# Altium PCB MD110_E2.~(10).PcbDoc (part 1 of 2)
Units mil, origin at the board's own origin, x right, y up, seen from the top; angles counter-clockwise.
Board outline 2320.51 x 1908 mil, 4 copper layers (Top Layer, Signal Layer 1, Signal Layer 2, Bottom Layer), stack 61.2 mil thick; 89 components, 32 nets, 187 pads, 40 vias.
Unrouted connection lines stored in the file: 7.
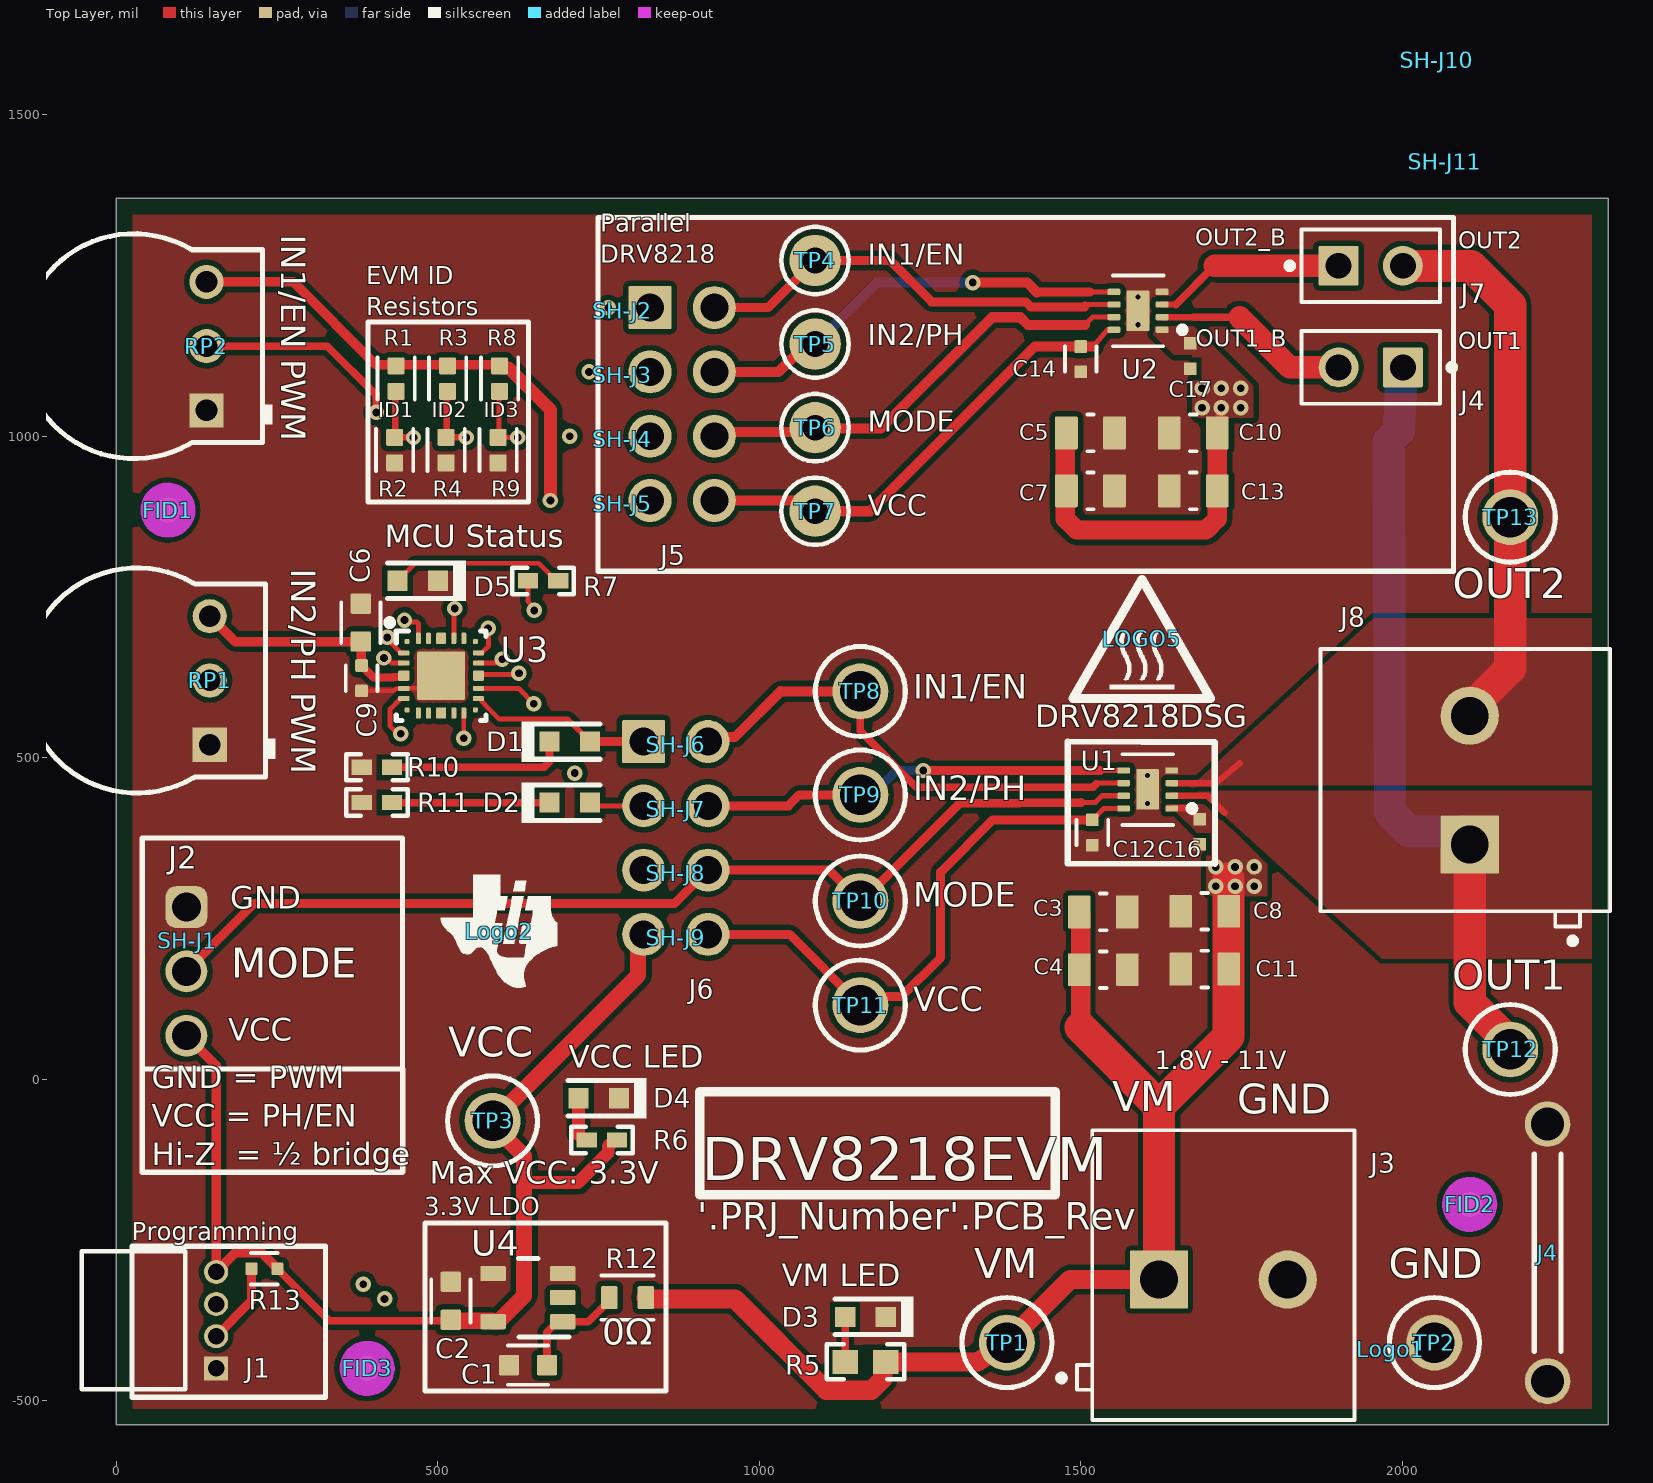
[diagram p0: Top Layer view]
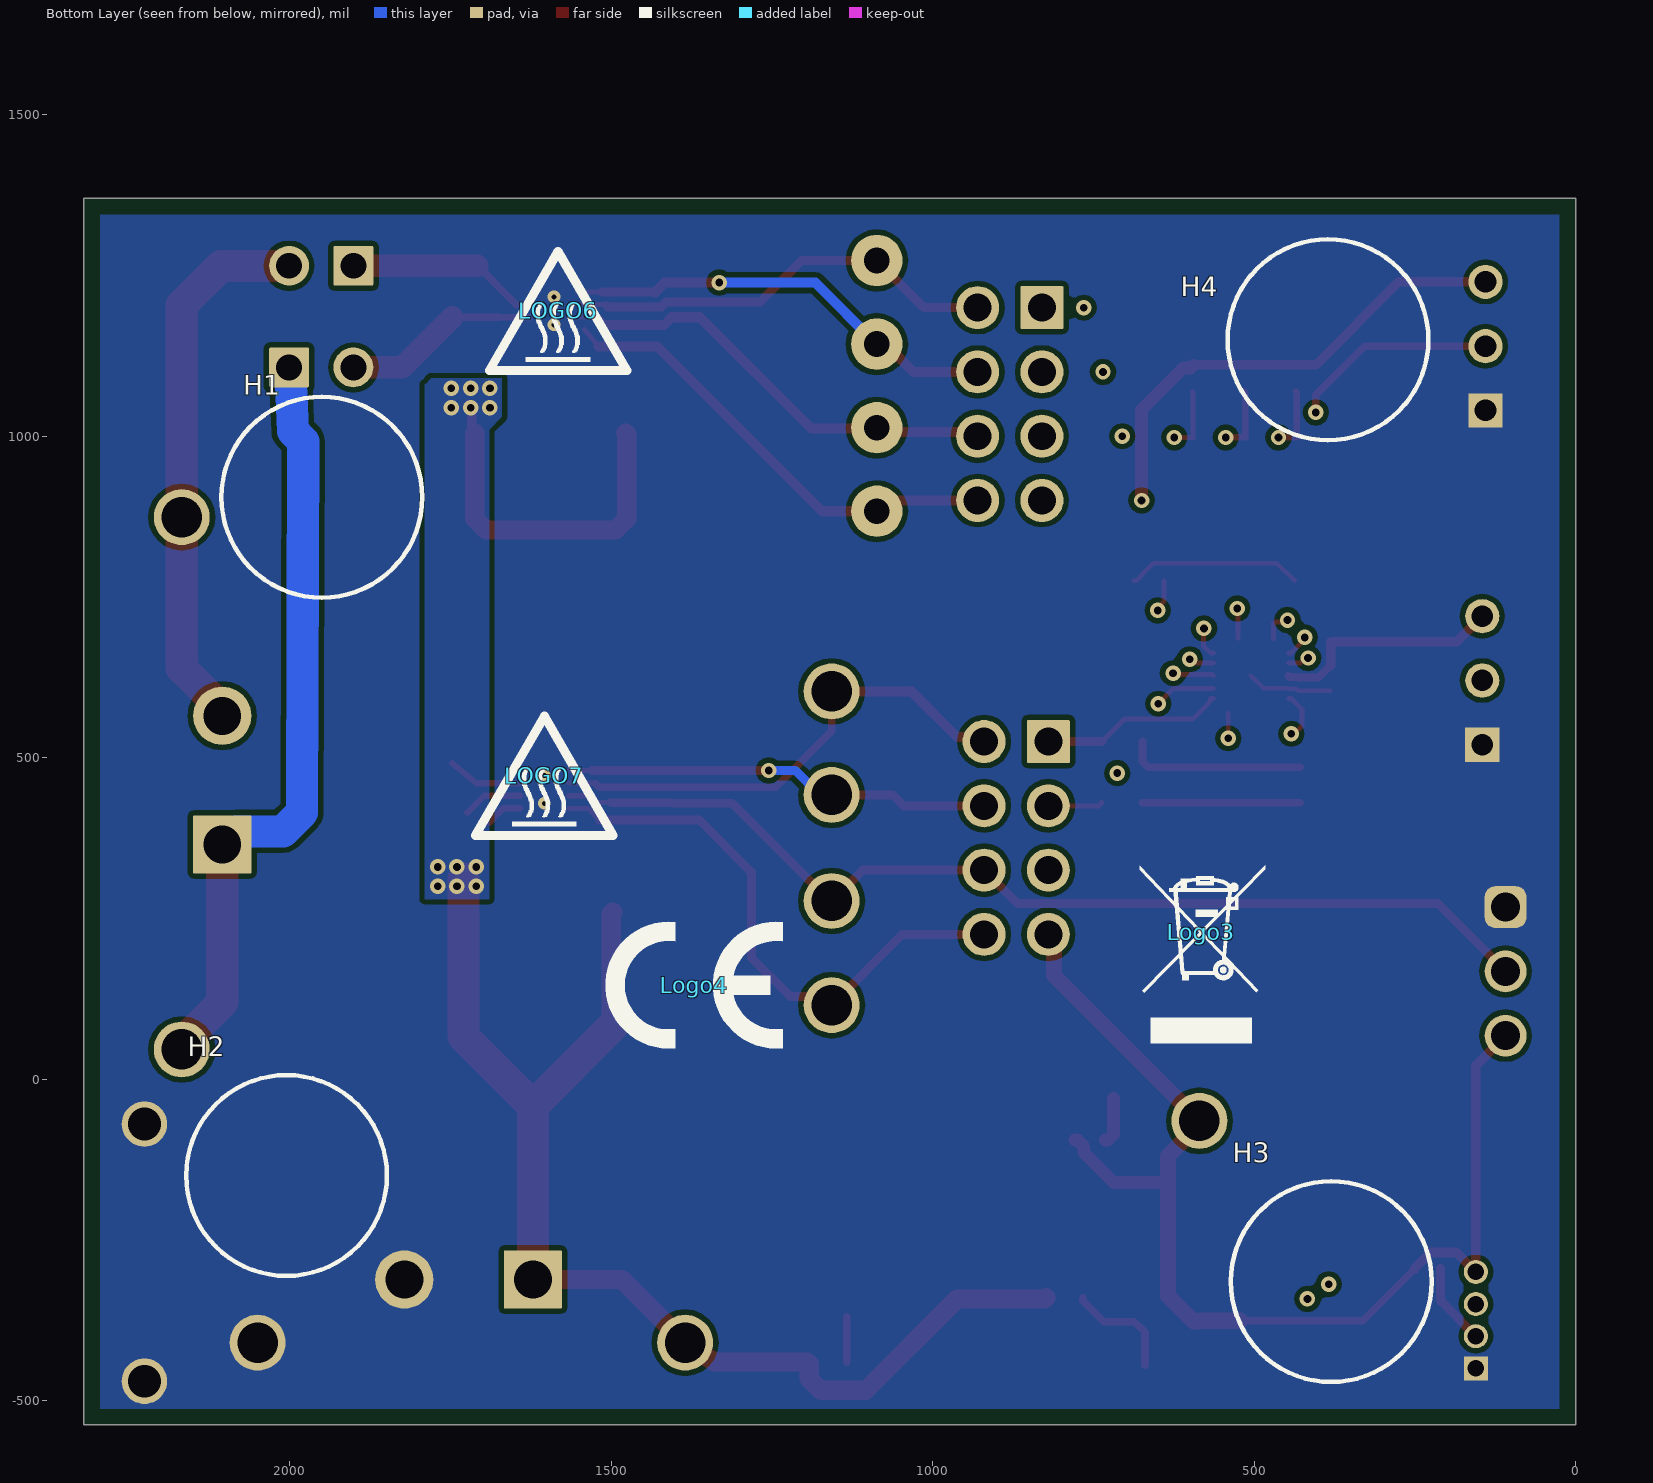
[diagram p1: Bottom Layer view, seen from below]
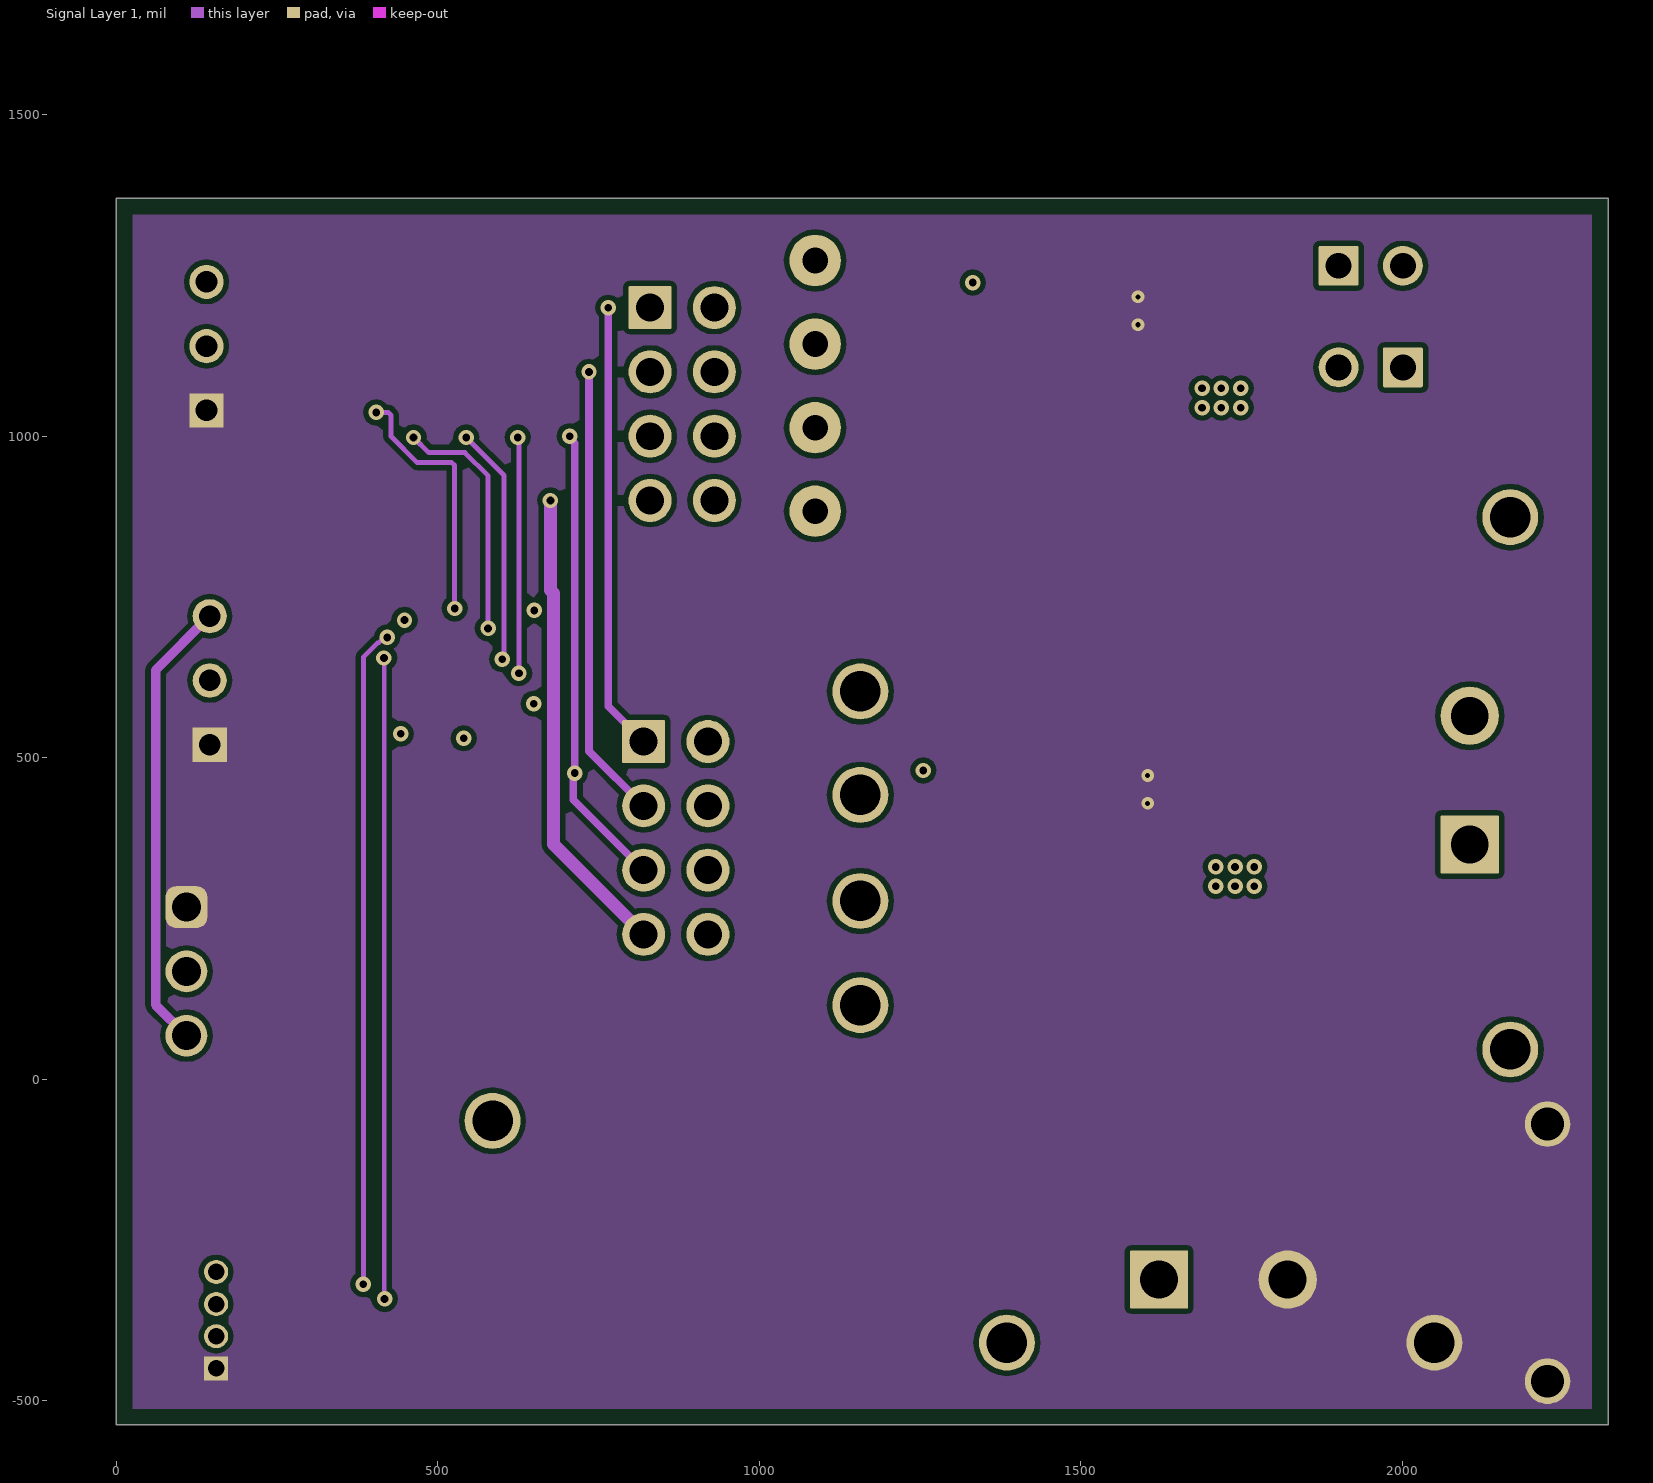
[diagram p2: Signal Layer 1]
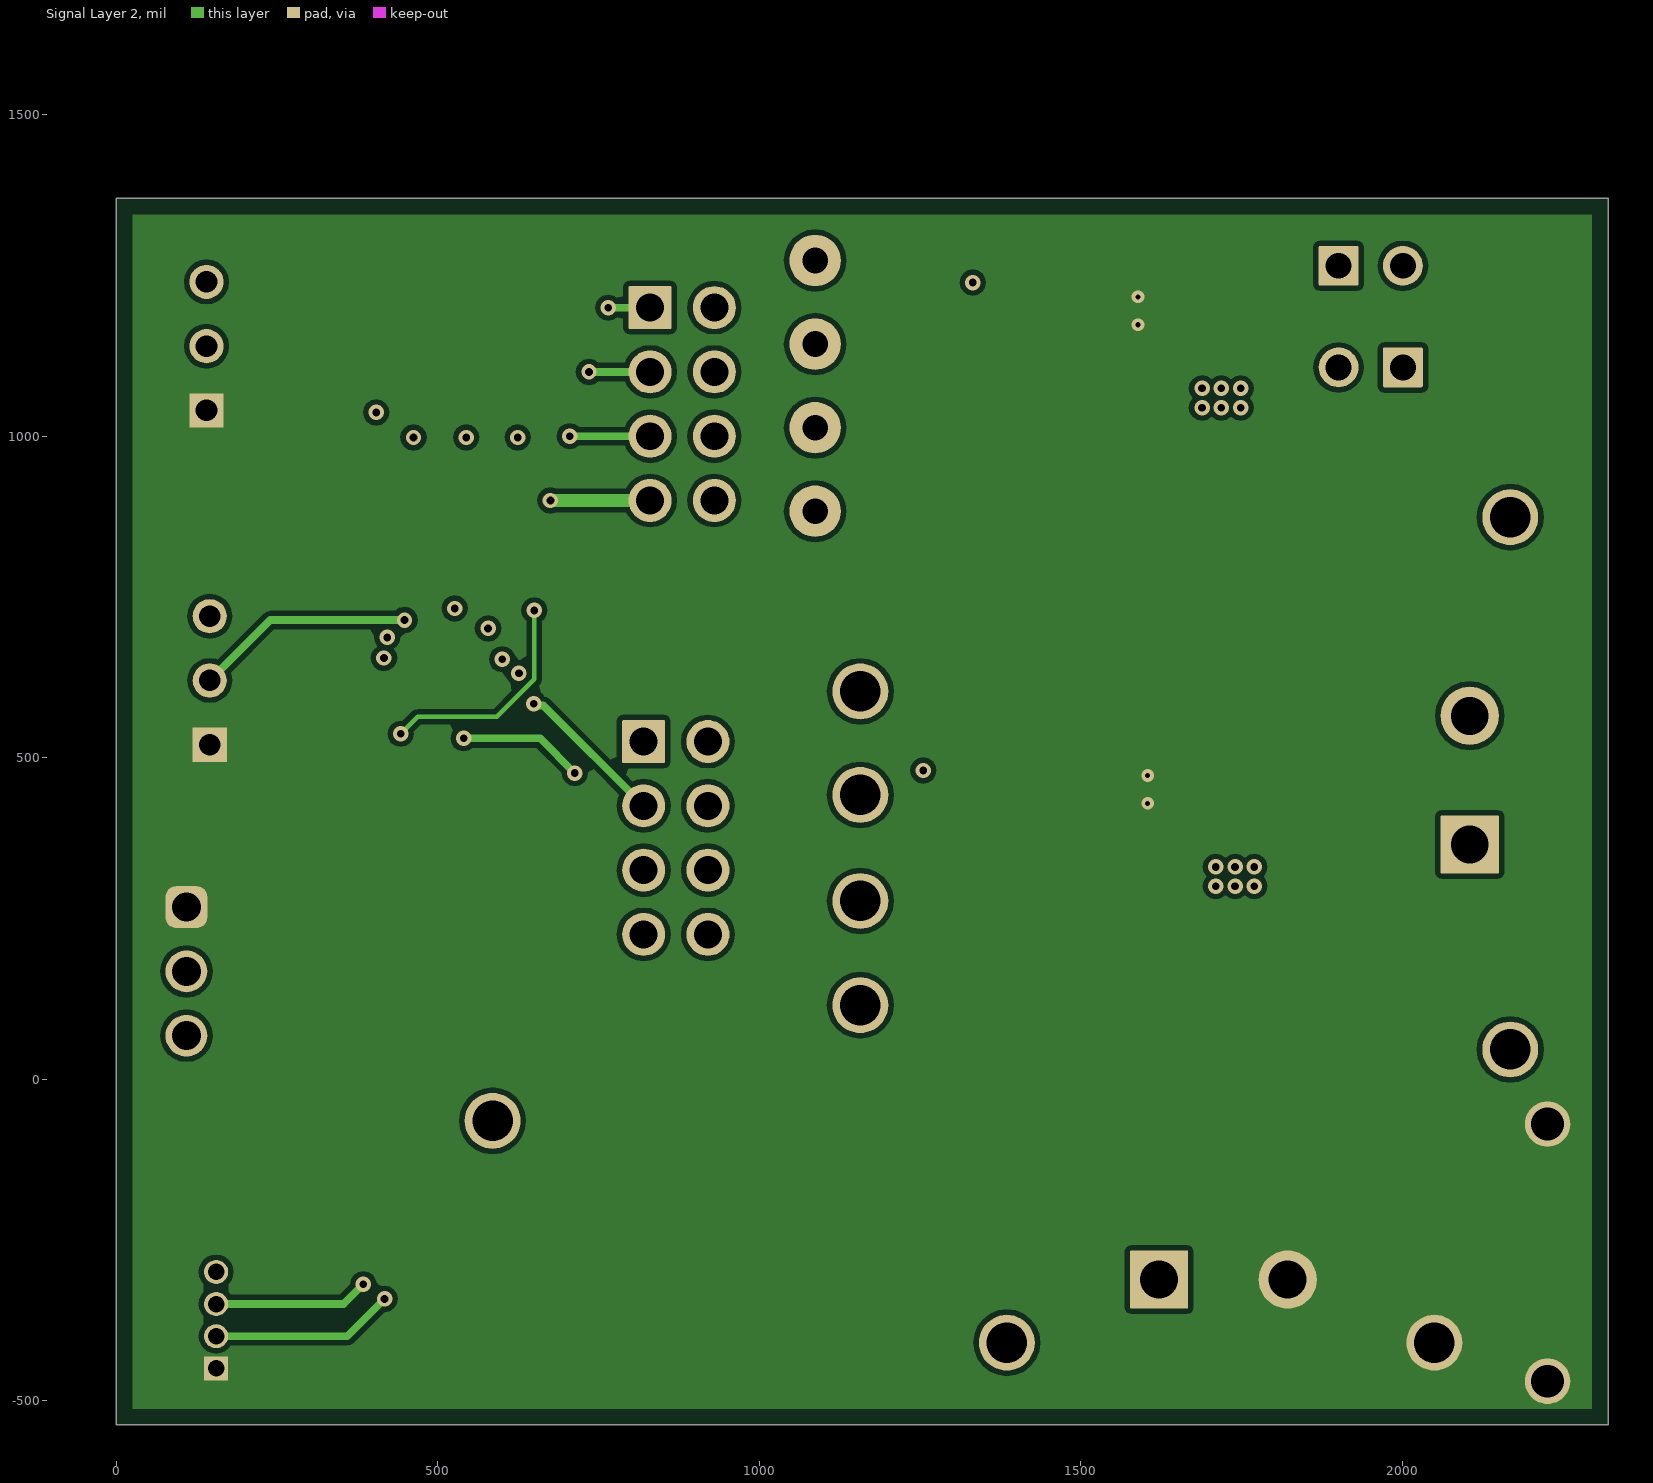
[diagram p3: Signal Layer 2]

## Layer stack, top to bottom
Top Solder: solder mask 0.4, Solder Resist, Dk 3.5
Top Layer: signal copper 2.8
Dielectric 1: prepreg 11.4, FR4 370, Dk 4.2
Signal Layer 1: signal copper 1.4
Dielectric 2: core 30, FR4 370, Dk 4.2
Signal Layer 2: signal copper 1.4
Dielectric 3: prepreg 11.4, FR4 370, Dk 4.2
Bottom Layer: signal copper 2.8
Bottom Solder: solder mask 0.4, Solder Resist, Dk 3.5

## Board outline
0,-538 0,1370 2320.51,1370 2320.51,-538

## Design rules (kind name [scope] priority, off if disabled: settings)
AcuteAngle [All] p1: minimum=4.50000000000000E+0001 checktracksonly=FALSE
AssemblyTestPointUsage [All] p1: valid=2
BoardOutlineClearance BoardOutlineClearance_MountingHoles [OnCopper and InComponentClass('Mounting Holes')] p1: gap=25 ignorepadtopadclearanceinfootprint=FALSE
BoardOutlineClearance BoardOutlineClearance_Poly [OnCopper and IsPoly] p2: gap=25 ignorepadtopadclearanceinfootprint=FALSE
BoardOutlineClearance [OnCopper and Not InComponentClass('Logo') and not InComponentClass('FiducialMark') and not InRegion(1000,500,4000,800) and not InPoly] p3: gap=10 ignorepadtopadclearanceinfootprint=FALSE
Clearance Clearance_OUTx [InNet('OUT1')] p1: gap=8 ignorepadtopadclearanceinfootprint=TRUE
Clearance Clearance_Keepouts [((IsTrack Or IsArc) And Not InPoly) And IsFree and IsKeepOut vs ((IsTrack Or IsArc) And Not InPoly) And IsFree and IsKeepOut] p2: gap=0 ignorepadtopadclearanceinfootprint=FALSE
Clearance Clearance_FiducialMark [IsKeepOut and InComponentClass('FiducialMark') vs IsPad and InComponentClass('FiducialMark')] p3: gap=0 ignorepadtopadclearanceinfootprint=FALSE
Clearance Clearance_Poly [InPolygon] p4: gap=8 ignorepadtopadclearanceinfootprint=TRUE
Clearance [All] p5: gap=7.87 ignorepadtopadclearanceinfootprint=TRUE
ComponentClearance ComponentClearance_Shunt2Header [InComponentClass('Header') vs InComponentClass('Shunt')] p1: gap=0 collisioncheckmode=3 verticalgap=0 showdistances=FALSE
ComponentClearance ComponentClearance_Shunt2Shunt [InComponentClass('Shunt') vs InComponentClass('Shunt')] p2: gap=0 collisioncheckmode=3 verticalgap=0 showdistances=FALSE
ComponentClearance ComponentClearance_MountingHoles_FiducialMarks [InComponentClass('Mounting Holes') vs InComponentClass('FiducialMark')] p3: gap=50 collisioncheckmode=3 verticalgap=10 showdistances=FALSE
ComponentClearance ComponentClearance_Logo [InComponentClass('Logo')] p4: gap=50 collisioncheckmode=3 verticalgap=10 showdistances=FALSE
ComponentClearance ComponentClearance_ScrewToNut [(HasFootprint('NY PMS 440 0025 PH')) vs (HasFootprint('Keystone_1902C'))] p5: gap=5 collisioncheckmode=3 verticalgap=10 showdistances=FALSE
ComponentClearance ComponentClearance_MountingHoles [InComponentClass('Mounting Holes')] p6: gap=250 collisioncheckmode=3 verticalgap=100000 showdistances=FALSE
ComponentClearance ComponentClearance_SmallPassives [HasFootprint('0201*') or HasFootprint('0402*') or HasFootprint('0508') or HasFootprint('0603*') or HasFootprint('0612') or HasFootprint('0805*') or HasFootprint('0815*') or HasFootprint('0830*') or HasFootprint('1206*') or HasFootprint('1210*') or HasFootprint('1808*') or HasFootprint('1812*') or HasFootprint('1825*') or HasFootprint('2010*') or HasFootprint('2220*') or HasFootprint('2225*') or HasFootprint('2512*') or HasFootprint('2728*') or HasFootprint('3518*') vs HasFootprint('0201*') or HasFootprint('0402*') or HasFootprint('0508') or HasFootprint('0603*') or HasFootprint('0612') or HasFootprint('0805*') or HasFootprint('0815*') or HasFootprint('0830*') or HasFootprint('1206*') or HasFootprint('1210*') or HasFootprint('1808*') or HasFootprint('1812*') or HasFootprint('1825*') or HasFootprint('2010*') or HasFootprint('2220*') or HasFootprint('2225*') or HasFootprint('2512*') or HasFootprint('2728*') or HasFootprint('3518*')] p7: gap=14.96 collisioncheckmode=3 verticalgap=10 showdistances=FALSE
ComponentClearance ComponentClearance_THtoSMT [IsThruComponent vs IsSMTComponent] p8: gap=30 collisioncheckmode=3 verticalgap=30 showdistances=FALSE
ComponentClearance ComponentClearance_THtoTH [IsThruComponent vs IsThruComponent] p9: gap=30 collisioncheckmode=3 verticalgap=30 showdistances=FALSE
ComponentClearance [All] p10: gap=30 collisioncheckmode=3 verticalgap=10 showdistances=FALSE
DiffPairsRouting [All] p1: maxlimit=100 minlimit=10 mostfreqgap=10 toplayer_minwidth=6.3 toplayer_maxwidth=15 toplayer_prefwidth=10 midlayer1_minwidth=15 midlayer1_maxwidth=15 midlayer1_prefwidth=15 midlayer2_minwidth=15 midlayer2_maxwidth=15 midlayer2_prefwidth=15 bottomlayer_minwidth=6.3 bottomlayer_maxwidth=15 bottomlayer_prefwidth=10 maxuncoupledlength=1000
FabricationTestPointUsage TestPointUsage [All] p1: valid=2 allowmultiple=FALSE
FabricationTestpoint Testpoint [All] p1: side=3 testpointundercomponent=TRUE minsize=40 maxsize=100 preferedsize=60 minholesize=0 maxholesize=40 preferedholesize=32 testpointgrid=1 allowsidetop=TRUE allowsidebottom=TRUE usegrid=TRUE gridtolerance=0.01
FanoutControl Fanout_LCC [IsLCC] p1: bgadir=Out bgaviamode=Centered fanoutstyle=Auto fanoutdirection=Alternating viagrid=1 // Fanout_LCC (Default Rule)
FanoutControl Fanout_BGA [IsBGA] p2: bgadir=Out bgaviamode=Centered fanoutstyle=Auto fanoutdirection=Alternating viagrid=1 // Fanout_BGA (Default Rule)
FanoutControl Fanout_Default [All] p4: bgadir=Out bgaviamode=Centered fanoutstyle=Auto fanoutdirection=Alternating viagrid=1 // Fanout_Default (Default Rule)
FanoutControl Fanout_Small [(CompPinCount < 5)] p5: bgadir=Out bgaviamode=Centered fanoutstyle=Auto fanoutdirection=OutThenIn viagrid=1 // Fanout_Small (Default Rule)
HoleSize [All] p1: absolutevalues=TRUE maxlimit=251 minlimit=7.87 maxpercent=80.000 minpercent=20.000
MinimumAnnularRing MinimumAnnularRing_ThermalPadVias [IsVia and InAnyComponent] p1: minimumring=5.91
MinimumAnnularRing [All] p2: minimumring=7.87
MinimumSolderMaskSliver MinimumSolderMaskSliver_Logo [InComponentClass('Logo') vs InComponentClass('Logo')] p1: minsoldermaskwidth=0.7
MinimumSolderMaskSliver [All] p2: minsoldermaskwidth=3.94
PlaneClearance [All] p1: clearance=12
PlaneConnect [All] p1: planeconnectstyle=Direct reliefexpansion=10 reliefentries=4 reliefconductorwidth=10 reliefairgap=10
PolygonConnect PolygonConnect_1 [InNetClass('Power-Net') vs IsNamedPolygon('TOP_LAYER_EZFET_USB_SHIELD_P201')] p1: connectstyle=Direct reliefconductorwidth=10 reliefentries=4 polygonreliefangle="90 Angle" airgapwidth=10
PolygonConnect [All] p2: connectstyle=Direct reliefconductorwidth=10 reliefentries=4 polygonreliefangle="90 Angle" airgapwidth=10
RoutingVias ThermalPadVias [IsVia and InAnyComponent] p1: holewidth=7.87 width=19.68 viastyle="Through Hole" minholewidth=7.87 minwidth=19.68 maxholewidth=12.99 maxwidth=23.62
RoutingVias [All] p2: holewidth=16 width=34 viastyle="Through Hole" minholewidth=7.87 minwidth=26 maxholewidth=40 maxwidth=65
SilkToBoardRegionClearance [Not ((IsComment or IsDesignator) And (Hide <> 'False')) and not InRegion(1000,500,4000,800)] p1:
SilkToSilkClearance SilkToSilkClearance_Pb-FreeLogo [(HasFootprint('Pb-Free_Overlay_Medium') OR HasFootprint('Pb-Free_Overlay_Small')) vs (HasFootprint('Pb-Free_Overlay_Medium') OR HasFootprint('Pb-Free_Overlay_Small'))] p1: silktosilkclearance=0
SilkToSilkClearance [All] p2: silktosilkclearance=3.94
SilkToSolderMaskClearance SilkToComponentPadClearance [(IsPad or IsFill or IsRegion) and InAnycomponent] p1: minsilkscreentomaskgap=5 clearancetoexposedcopper=TRUE
SilkToSolderMaskClearance "Silk to Solder Mask Opening" [All] p2: minsilkscreentomaskgap=3.94 clearancetoexposedcopper=FALSE
SolderMaskExpansion [All] p1: expansion=1.97 istentingtop=FALSE
UnRoutedNet [All] p1: checkbadconnections=TRUE
Width [All] p1: maxlimit=65 minlimit=4 preferedwidth=15 minimp=50.000000 maximp=50.000000 favimp=50.000000 checkconnectedcopper=TRUE
13 further rules are at their usual default settings.

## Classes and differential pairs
component class Shunt: SH-J1 SH-J2 SH-J3 SH-J4 SH-J5 SH-J6 SH-J7 SH-J8 SH-J9 SH-J10 SH-J11
component class MD110_E2_Schematic: C1 C2 C3 C4 C5 C6 C7 C8 C9 C10 C11 C12 C13 C14 C16 C17 D1 D2 D3 D4 D5 J1 J2 J3 J4 J5 J6 J7 J8 R1 R2 R3 R4 R5 R6 R7 R8 R9 R10 R11 R12 R13 RP1 RP2 SH-J1 SH-J2 SH-J3 SH-J4 SH-J5 SH-J6 SH-J7 SH-J8 SH-J9 SH-J10 SH-J11 TP1 TP2 TP3 TP4 TP5 TP6 TP7 TP8 TP9 TP10 TP11 TP12 TP13 U1 U2 U3 U4
component class FiducialMark: FID1 FID2 FID3
component class MD110_E2_Hardware: !PCB1 FID1 FID2 FID3 H1 H2 H3 H4 Logo1 Logo2 Logo3 Logo4 LOGO5 LOGO6 LOGO7 ZZ1 ZZ5
component class Header: J2 J5 J6
component class Logo: Logo2
component class AssemblyNote: ZZ1 ZZ5

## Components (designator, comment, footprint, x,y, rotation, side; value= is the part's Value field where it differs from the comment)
C1 "885012206126" FP-885012206126_0603-MFG 640,-445 r0 top value=1µF
C2 "885012106012" FP-885012106012_0603-MFG 520,-345 r270 top value=4.7µF
C3 "885012107019" FP-885012107019_0805-MFG 1535,260 r0 top value=22µF
C4 "885012107019" FP-885012107019_0805-MFG 1535,170 r0 top value=22µF
C5 "885012107019" FP-885012107019_0805-MFG 1515,1005 r0 top value=22µF
C6 "885012206126" FP-885012206126_0603-MFG 380,710 r270 top value=1µF
C7 "885012107019" FP-885012107019_0805-MFG 1515,915 r0 top value=22µF
C8 "885012107019" FP-885012107019_0805-MFG 1692.72,261.06 r180 top value=22µF
C9 "885012205018" FP-885012205018_0402-MFG 381.22,623.53 r90 top value=100nF
C10 "885012107019" FP-885012107019_0805-MFG 1675,1005 r180 top value=22µF
C11 "885012107019" FP-885012107019_0805-MFG 1692.72,171.06 r180 top value=22µF
C12 "885012205018" FP-885012205018_0402-MFG 1518,383.5 r90 top value=100nF
C13 "885012107019" FP-885012107019_0805-MFG 1675,915 r180 top value=22µF
C14 "885012205018" FP-885012205018_0402-MFG 1500,1119.76 r90 top value=100nF
C16 "885012205085" WCAP-CSGP_0402_L1W0.5H0.5 1685,384.68 r90 top value=100nF
C17 "885012205085" WCAP-CSGP_0402_L1W0.5H0.5 1670,1124.68 r90 top value=100nF
D1 "150060BS75000" WL-SMCW_Blue 705,525 r0 top value=Blue
D2 "150060BS75000" WL-SMCW_Blue 705,430 r0 top value=Blue
D3 "150060VS75000" WL-SMCW_GREEN 1165,-370 r180 top value=Green
D4 "150060VS75000" WL-SMCW_GREEN 750,-30 r180 top value=Green
D5 "150060VS75000" WL-SMCW_GREEN 468.5,775 r180 top value=Green
FID1 "Fiducial" Fiducial10-20 80,885 r90 top
FID2 "Fiducial" Fiducial10-20 2105,-195 r90 top
FID3 "Fiducial" Fiducial10-20 390,-450 r90 top
H1 "SJ61A1" Bumpon_SJ61A1 1950,905 r180 bottom
H2 "SJ61A1" Bumpon_SJ61A1 2005,-150 r180 bottom
H3 "SJ61A1" Bumpon_SJ61A1 380,-315 r180 bottom
H4 "SJ61A1" Bumpon_SJ61A1 385,1150 r180 bottom
J1 "851-43-004-20-001000" CONN_851-43-004-20-001000 155,-375 r270 top
J2 "61300311121" WURTH_61300311121 108.76,167.48 r270 top
J3 "691236510002" FP-691236510002_HHR2-MFG 1710,-305 r0 top
J4 "PH1-02-UA" FP-PH1-02-UA_HDR2-MFG 1951,1107 r180 top
J4 "D3082-05" Harwin_D3082-05 2226,-270 r270 top
J5 "61300821121" FP-61300821121_HDR8-MFG 880,1050 r270 top
J6 "61300821121" FP-61300821121_HDR8-MFG 870,375 r270 top
J7 "PH1-02-UA" FP-PH1-02-UA_HDR2-MFG 1951,1265 r0 top
J8 "691236510002" FP-691236510002_HHR2-MFG 2098.11,453.19 r90 top
Logo1 "FCC disclaimer" FCC_disclaimer 1982,-420 r180 top
Logo2 "Texas Instruments" TI_Symbol_Overlay_Small 595,230 r0 top
Logo3 "WEEE logo" WEEE_Minimum 582,228 r180 bottom
Logo4 "CE Mark" CE_Mark_5mm 1371,146 r180 bottom
LOGO5 "CAUTION HOT SURFACE" IEC_HotSurface_Small 1595,685 r0 top
LOGO6 "CAUTION HOT SURFACE" IEC_HotSurface_Small 1582.6,1194.84 r180 bottom
LOGO7 "CAUTION HOT SURFACE" IEC_HotSurface_Small 1604,472.15 r180 bottom
R1 "CR0402-10W-000T" FP-CR0402-10W-000T_0402-IPC_A 434.94,1089.58 r90 top value=0Ω
R2 "CR0402-10W-000T" FP-CR0402-10W-000T_0402-IPC_A 432.71,978.27 r90 top value=0Ω
R3 "CR0402-10W-000T" FP-CR0402-10W-000T_0402-IPC_A 514.94,1089.58 r90 top value=0Ω
R4 "CR0402-10W-000T" FP-CR0402-10W-000T_0402-IPC_A 512.71,978.27 r90 top value=0Ω
R5 "ESR03EZPJ102" 0603 1165,-440 r180 top value=1.0k
R6 "CRCW0402330RFKED" 0402 755,-95 r180 top value=330
R7 "CRCW0402330RFKED" 0402 663.62,775 r0 top value=330
R8 "CR0402-10W-000T" FP-CR0402-10W-000T_0402-IPC_A 595.95,1089.58 r90 top value=0Ω
R9 "CR0402-10W-000T" FP-CR0402-10W-000T_0402-IPC_A 593.73,978.27 r90 top value=0Ω
R10 "CRCW0402330RFKED" 0402 405,485 r180 top value=330
R11 "CRCW0402330RFKED" 0402 405,430 r180 top value=330
R12 "ERJ-3GEY0R00V" FP-ERJ-3GEY0R00V_0603-MFG 795,-340 r180 top value=0Ω
R13 "ERJ-2GEJ473X" FP-ERJ-2GEJ473X_0402-MFG 230,-295 r180 top value=47k
RP1 "3352T-1-503LF" Bourns_3352T 145,620 r90 top value=50k
RP2 "3352T-1-503LF" Bourns_3352T 140,1140 r90 top value=50k
SH-J1 "60900213421" Wurth_60900213421 110,215 r270 top
SH-J2 "60900213421" Wurth_60900213421 786.54,1195 r180 top
SH-J3 "60900213421" Wurth_60900213421 786.54,1095 r180 top
SH-J4 "60900213421" Wurth_60900213421 786.54,995 r180 top
SH-J5 "60900213421" Wurth_60900213421 786.54,895 r180 top
SH-J6 "60900213421" Wurth_60900213421 870,520 r180 top
SH-J7 "60900213421" Wurth_60900213421 870,420 r180 top
SH-J8 "60900213421" Wurth_60900213421 870,320 r180 top
SH-J9 "60900213421" Wurth_60900213421 870,220 r180 top
SH-J10 "60900213421" Wurth_60900213421 2054,1585 r180 top
SH-J11 "60900213421" Wurth_60900213421 2066,1427 r180 top
TP1 "5010" Keystone5010 1385,-410 r180 top
TP2 "5011" Keystone5011 2050,-410 r0 top
TP3 "5013" Keystone5013 585,-65 r0 top
TP4 "5002" Keystone5002 1086.72,1273.28 r90 top
TP5 "5002" Keystone5002 1086.72,1143.28 r90 top
TP6 "5002" Keystone5002 1086.72,1013.28 r90 top
TP7 "5002" Keystone5002 1086.72,883.28 r90 top
TP8 "5012" Keystone5012 1157,603 r90 top
TP9 "5012" Keystone5012 1157,442 r90 top
TP10 "5012" Keystone5012 1157,277 r90 top
TP11 "5012" Keystone5012 1157,115 r90 top
TP12 "5012" Keystone5012 2168,46 r0 top
TP13 "5012" Keystone5012 2168,874 r0 top
U1 "DRV8218DSGR" DSG0008A-MFG 1604,450.5 r180 top
U2 "DRV8218DSGR" DSG0008A-MFG 1589,1195 r180 top
U3 "MSP430FR2100IRLLR" RLL0024A 505,627.4 r0 top
U4 "TPS7B6933DBVR" DBV0005A_N 640,-340 r180 top
ZZ1 "These assemblies are ESD sensitive, ESD precautions shall be observed." AssemblyNote 421,-858 r0 top
ZZ5 "This Assembly Note is for PCB labels only" AssemblyNoteLabel 490,-758 r0 top

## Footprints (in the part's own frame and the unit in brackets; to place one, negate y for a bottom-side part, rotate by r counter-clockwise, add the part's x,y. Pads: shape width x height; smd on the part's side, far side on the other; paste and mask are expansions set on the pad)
0402 [mm] "0402 from SM-752 data"
  rect 0.8x0.6 smd: 1(-0.6,0) 2(0.6,0)
  silkscreen extent -1.22,-0.52 1.22,0.52, body extent -0.55,-0.3 0.55,0.3, height 0.6
0603 [mm] "0603 from SM-752 data"
  rect 1x0.95 smd: 1(-0.8,0) 2(0.8,0)
  silkscreen extent -1.52,-0.69 1.52,0.69, body extent -0.87,-0.47 0.87,0.47, height 1
AssemblyNote [mil] "Assembly Note"
AssemblyNoteLabel [mil] "Assembly Note for PCB Labels"
Bourns_3352T [mm] "TH, 3-Leads, Body 9.53x8.89mm, Pitch 2.54mm"
  rect 1.35x1.35 hole 0.85: 1(-2.54,0)
  round 1.35 hole 0.85: 2(0,0) 3(2.54,0)
  silkscreen extent -4.44,-2.6 4.44,7.31, body extent -4.44,-2.21 4.45,7.32, height 3.81
Bumpon_SJ61A1 [mil] "3M Cylindrical Bumpon black"
  round 1 on Mech4: 0(0,0)
  silkscreen extent -156,-156 156,156, body extent -156,-156 156,156, height 201
CE_Mark_5mm [mil] "Minimum text height for CE Mark"
  silkscreen extent -138,-98 138,98
CONN_851-43-004-20-001000 [mm] "MILL-MAX"
  rect 0.95x0.95 hole 0.65: 1(1.905,0)
  round 0.95 hole 0.65: 2(0.635,0) 3(-0.635,0) 4(-1.905,0)
  silkscreen extent -2.73,-5.31 2.73,-1.22, body extent -2.73,-5.31 2.73,0.23, height 2.23
DBV0005A_N [mm] "SOT23, 5-Leads, Body 2.9x1.6mm, Pitch 0.95mm, Lead Span 2.8mm, IPC Medium Density"
  rrect17% 1x0.6 smd: 1(-1.375,0.95) 2(-1.375,0) 3(-1.375,-0.95) 4(1.375,-0.95) 5(1.375,0.95)
  silkscreen extent -1.63,-1.55 0.38,1.55, body extent -1.42,-1.46 1.42,1.46, height 1.09
DSG0008A-MFG [mm] "Recommended Land Pattern"
  rrect40% 0.5x0.25 smd paste+0 mask+0: 1(-0.95,0.75) 2(-0.95,0.25) 3(-0.95,-0.25) 4(-0.95,-0.75) 5(0.95,-0.75) 6(0.95,-0.25) 7(0.95,0.25) 8(0.95,0.75)
  rrect11% 0.9x1.6 smd paste-1000 mask+0: 9(0,0)
  silkscreen extent -1.88,-1.39 1,1.4, body extent -1,-1 1,1, height 0.8
FCC_disclaimer [mil]
Fiducial10-20 [mm]
  round 1 smd mask+0.5: 1(0,0)
  Top Layer keep-out circle w1.178: c0,0 r0.5
FP-61300821121_HDR8-MFG [mm]
  rrect6% 1.7x1.7 hole 1.1 paste-2539.97 mask+0: 1(-3.81,-1.27)
  round 1.7 hole 1.1 paste-2539.97 mask+0: 2(-3.81,1.27) 3(-1.27,-1.27) 4(-1.27,1.27) 5(1.27,-1.27) 6(1.27,1.27) 7(3.81,-1.27) 8(3.81,1.27)
  body extent -5.33,-2.72 5.33,2.72, height 0.25
FP-691236510002_HHR2-MFG [mm]
  rrect4% 2.3x2.3 hole 1.5 paste-2539.97 mask+0: 1(-2.24,-0.175)
  round 2.3 hole 1.5 paste-2539.97 mask+0: 2(2.84,-0.175)
  silkscreen extent -6.22,-5.72 5.48,5.72, body extent -5.58,-5.82 5.58,5.82, height 0.25
FP-885012106012_0603-MFG [mm]
  rrect13% 0.8x0.8 smd paste+0 mask+0: 1(-0.75,0) 2(0.75,0)
  silkscreen extent -0.85,-0.77 0.85,0.77, body extent -1.25,-0.55 1.25,0.55, height 0.25
FP-885012107019_0805-MFG [mm] "Recommended Land Pattern"
  rrect11% 0.9x1.3 smd paste+0 mask+0: 1(-0.95,0) 2(0.95,0)
  silkscreen extent -0.13,-0.72 0.13,0.72, body extent -1.5,-0.82 1.5,0.82, height 0.25
FP-885012205018_0402-MFG [mm]
  rrect20% 0.5x0.5 smd paste+0 mask+0: 1(-0.5,0) 2(0.5,0)
  silkscreen extent -0.5,-0.63 0.5,0.63, body extent -0.85,-0.38 0.85,0.38, height 0.25
FP-885012206126_0603-MFG [mm]
  rrect13% 0.8x0.8 smd paste+0 mask+0: 1(-0.75,0) 2(0.75,0)
  silkscreen extent -0.8,-0.77 0.8,0.77, body extent -1.25,-0.58 1.25,0.58, height 0.25
FP-CR0402-10W-000T_0402-IPC_A [mil]
  rrect15% 26.19x26.48 smd paste+0 mask+0: 1(-19.83,0) 2(19.83,0)
  silkscreen extent -33,-29 33,29, body extent -41,-21 41,21, height 10
FP-ERJ-2GEJ473X_0402-MFG [mm]
  rrect21% 0.475x0.5 smd paste+0 mask+0: 1(-0.513,0) 2(0.513,0)
  silkscreen extent -0.53,-0.63 0.53,0.63, body extent -0.85,-0.38 0.85,0.38, height 0.25
FP-ERJ-3GEY0R00V_0603-MFG [mm]
  rrect15% 0.65x0.9 smd paste+0 mask+0: 1(-0.725,0) 2(0.725,0)
  silkscreen extent -1.03,-0.87 1.03,0.87, body extent -1.15,-0.58 1.15,0.58, height 0.25
FP-PH1-02-UA_HDR2-MFG [mm]
  rrect6% 1.57x1.57 hole 1.02 paste-1000 mask+0: 1(-1.27,0)
  round 1.57 hole 1.02 paste-1000 mask+0: 2(1.27,0)
  silkscreen extent -3.33,-1.44 2.73,1.44, body extent -2.83,-1.54 2.83,1.54, height 0.25
Harwin_D3082-05 [mm] "Shorting Plug, 10.16mm spacing, TH"
  round 1.8 hole 1.3: 1(-5.08,0) 2(5.08,0)
  silkscreen extent -3.9,-0.53 3.9,0.53, body extent -5.6,-0.52 5.61,0.52, height 6.63
IEC_HotSurface_Small [mil]
  silkscreen extent -107,-93 107,92
Keystone5002 [mil] "For Keystone 500x miniature loop terminals"
  round 80 hole 40: 1(0,0)
  silkscreen extent -52,-52 52,52, body extent -49,-49 49,49, height 182
Keystone5010 [mil] "Keystone Multipurpose loops"
  round 87 hole 63: 1(0,0)
  silkscreen extent -70,-70 70,70, body extent -63,-63 63,62, height 319
Keystone5011 [mil] "Keystone Multipurpose loops"
  round 87 hole 63: 1(0,0)
  silkscreen extent -70,-70 70,70, body extent -63,-63 63,62, height 319
Keystone5012 [mil] "Keystone Multipurpose loops"
  round 87 hole 63: 1(0,0)
  silkscreen extent -70,-70 70,70, body extent -63,-63 63,62, height 319
Keystone5013 [mil] "Keystone Multipurpose loops"
  round 87 hole 63: 1(0,0)
  silkscreen extent -70,-70 70,70, body extent -63,-63 63,62, height 319
RLL0024A [mm] "QFN, 24-Leads, Body 3x3mm"
  rrect50% 0.45x0.2 smd: 1(-1.475,0.9) 2(-1.475,0.5) 4(-1.475,-0.5) 5(-1.475,-0.9) 13(1.475,-0.9) 14(1.475,-0.5) 16(1.475,0.5) 17(1.475,0.9)
  rrect25% 0.45x0.4 smd: 3(-1.475,0) 15(1.475,0)
  rrect50% 0.2x0.2 smd: 6(-1.35,-1.35) 12(1.35,-1.35) 18(1.35,1.35) 24(-1.35,1.35)
  rrect50% 0.2x0.45 smd: 7(-0.9,-1.475) 8(-0.5,-1.475) 10(0.5,-1.475) 11(0.9,-1.475) 19(0.9,1.475) 20(0.5,1.475) 22(-0.5,1.475) 23(-0.9,1.475)
  rrect25% 0.4x0.45 smd: 9(0,-1.475) 21(0,1.475)
  rrect5% 1.9x1.9 smd paste-1.9: 25(0,0)
  rrect6% 1.71x1.71 on Top Paste: ""(0,0)
  silkscreen extent -1.78,-1.78 1.78,1.78, body extent -1.58,-1.58 1.58,1.58, height 1.01
TI_Symbol_Overlay_Small [mil]
  silkscreen extent -90,-88 91,88
WCAP-CSGP_0402_L1W0.5H0.5 [mm] "Ceramic Capacitors, body 1x0.5mm"
  rect 0.5x0.5 smd: 1(-0.5,0) 2(0.5,0)
  body extent -0.5,-0.25 0.5,0.25, height 0.5
WEEE_Minimum [mil] "WEEElie bin"
  silkscreen extent -95,-172 99,104
WL-SMCW_Blue [mm] "SMD, 2-Leads, Body 1.6x0.8mm"
  rect 0.8x0.8 smd: 1(-0.8,0) 2(0.8,0)
  silkscreen extent -1.9,-0.8 1.2,0.8, body extent -0.85,-0.45 0.85,0.45, height 0.8
WL-SMCW_GREEN [mm] "WURTH"
  rect 0.8x0.8 smd: 1(-0.8,0) 2(0.8,0)
  silkscreen extent -1.9,-0.8 1.2,0.8, body extent -0.85,-0.45 0.85,0.45, height 0.8
Wurth_60900213421 [mil] "Shunt, 2.54mm, Black"
  round 1 on Mech3: 0(0,0)
  body extent -98,-48 98,48, height 338
WURTH_61300311121 [mm] "Header, 2.54mm, 3x1, TH"
  rrect50% 1.65x1.65 hole 1.15: 1(-2.54,0)
  round 1.65 hole 1.15: 2(0,0) 3(2.54,0)
  body extent -3.81,-1.27 3.81,1.27, height 8.54

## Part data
C1 C6: library part CMP-0120896-1, "1 µF ±10% 50V Ceramic Capacitor X7R 0603 (1608 Metric)", Digikey Part Number=732-885012206126CT-ND, Manufacturer="Wurth Electronics", Mouser Part Number=710-885012206126, Operating Temperature Range="-55°C to +125°C", TempCo=15%, Temperature Characteristic=X7R, Tolerance_%=10%, ValueDisplayed=1uF
C2: library part CMP-0097305-1, "4.7 µF ±20% 10V Ceramic Capacitor X5R 0603 (1608 Metric)", Digikey Part Number=732-7909-1-ND, Manufacturer="Wurth Electronics", Mouser Part Number=710-885012106012, Operating Temperature Range="-55°C to +85°C", TempCo=15%, Temperature Characteristic=X5R, Tolerance_%=20%, ValueDisplayed=4.7uF
C3 C4 C5 C7 C8 C10 C11 C13: library part CMP-0124987-1, "Ceramic Capacitor 0805 22µF ±20% 25V X5R", Manufacturer=Wurth, Operating Temperature Range="-55°C to +85°C", TempCo=15%, Temperature Characteristic=X5R, Tolerance_%=20%, ValueDisplayed=22uF
C9 C12 C14: library part CMP-0090362-1, "0.1µF ±10% 10V Ceramic Capacitor X7R 0402 (1005 Metric)", Digikey Part Number=732-7513-1-ND, Manufacturer="Wurth Electronics", Mouser Part Number=710-885012205018, Operating Temperature Range="-55°C to +125°C", TempCo=15%, Temperature Characteristic=X7R, Tolerance_%=10%, ValueDisplayed=100000pF
C16 C17: library part CMP-0111807-1, "WCAP-CSGP Multilayer Ceramic Chip Capacitor, General Purpose, size 0402, X7R, 100nF, 25VDC", Capacitance Tolerance=+/-10%, Insulation Resistance=5GOhm, Manufacturer="Wurth Elektronik", Operating Temperature Max=125°C, Operating Temperature Min=-55°C, Rated Voltage (DC)=25V
D1 D2: library part CMP-0002946-3, "LED, Blue, SMD", Color=Blue, Manufacturer="Wurth Elektronik", Power_TotalModule=105mW, Value1=0.105W, Value2=3.2V
D3 D4 D5: library part CMP-0002894-2, "LED, Green, SMD", Color=green, Manufacturer="Wurth Elektronik", Value1=W, Value2=2V
FID1 FID2 FID3: library part CMP-0077181-1, "Fiducial mark.  There is nothing to buy or mount.", Manufacturer=N/A
H1 H2 H3 H4: library part CMP-0003621-1, "Bumpon, Cylindrical, 0.312 X 0.200, Black", Manufacturer=3M, Supplier Part Number 1=SJ5746-0-ND
J1: library part CMP-0055060-1, "SOCKET .050\" GRID SIP 4 POS R/A, TH", Manufacturer=Mill-Max, Supplier Part Number 1=ED90474-ND
J2: library part CMP-0054796-4, "Header, 2.54 mm, 3x1, Gold, TH", Manufacturer="Wurth Elektronik", Supplier Part Number 1=732-5316-ND
J3 J8: library part CMP-0121282-1, "2 Position Wire to Board Terminal Block Horizontal with Board 0.200\" (5.08mm) Through Hole", Current_A=20A, Digikey Part Number=732-10995-ND, Manufacturer="Wurth Electronics", Mouser Part Number=710-691236510002, Operating Temperature Range="-30°C to +120°C", Voltage_V=300V
J4 J7: library part CMP-0032636-1, "Connector Header Through Hole 2 position 0.100\" (2.54mm)", Current_A=3A, Digikey Part Number=2057-PH1-02-UA-ND, Manufacturer="Adam Tech", Operating Temperature Range=to, Voltage_V=250V
J4: library part CMP-0075110-1, "1mm Uninsulated Shorting Plug, 10.16mm spacing, TH", Manufacturer=Harwin, Supplier Part Number 1=952-1873-ND
J5 J6: library part CMP-0087153-1, "CONN HEADER VERT 8POS 2.54MM", Current_A=3A, Manufacturer="Wurth Electronics", Voltage_V=250V
Logo1: library part CMP-0074847-1, "FCC_disclaimer"
Logo2: library part CMP-0074838-1, "Texas Instrument Corporate Signature"
Logo3: library part CMP-0074769-4, Manufacturer="Texas Instruments"
Logo4: library part CMP-0074844-2, Manufacturer="Texas Instruments"
LOGO5 LOGO6 LOGO7: library part CMP-0074837-2, "IEC 61010-1 Hot Surface Warning", Manufacturer="Texas Instruments"
R1 R2 R3 R4 R8 R9: library part CMP-0094948-1, "0 Ohms Jumper 0.1W, 1/10W Chip Resistor 0402 (1005 Metric) - Thick Film", Digikey Part Number=2679-CR0402-10W-000TTR-ND, Manufacturer=Venkel, Operating Temperature Range="-55°C to +155°C", Power_W=100mW
R5: library part CMP-0084244-1, "RES, 1.0 k, 5%, 0.25 W, AEC-Q200 Grade 0, 0603", Manufacturer=Rohm, Power_W=250mW, TempCo="200 ppm/C", Tolerance_%=5%, Value2=0.25W, Value_Code=1k00, ValueDisplayed=1.0k
R6 R7 R10 R11: library part CMP-0078658-2, "RES, 330, 1%, 0.063 W, AEC-Q200 Grade 0, 0402", Manufacturer=Vishay-Dale, Power_W=63mW, Supplier Part Number 1=541-330LCT-ND, TempCo="100 ppm/C", Tolerance_%=1%, Value2=0.063W, Value_Code=330R, ValueDisplayed=330
R12: library part CMP-0089143-1, "0 Ohms Jumper 0.1W, 1/10W Chip Resistor 0603 (1608 Metric) Automotive AEC-Q200 Thick Film", Digikey Part Number=P0.0GCT-ND, Manufacturer=Panasonic, Mouser Part Number=667-ERJ-3GEY0R00V, Operating Temperature Range="-55°C to +155°C", Power_W=100mW, TempCo=-100/+600ppm/°C, Tolerance_%=5%
R13: library part CMP-0122885-1, "47 kOhms ±5% 0.1W, 1/10W Chip Resistor 0402 (1005 Metric) Automotive AEC-Q200 Thick Film", Digikey Part Number=P47KJCT-ND, Manufacturer=Panasonic, Mouser Part Number=667-ERJ-2GEJ473X, Operating Temperature Range="-55°C to +155°C", Power=100mW, TempCo=200ppm/°C, Tolerance_%=5%
RP1 RP2: library part CMP-0001777-2, "Trimming Potentiometer, 50K, 0.5W, TH", Manufacturer=Bourns, Supplier Part Number 1=3352T-503LF-ND
SH-J1 SH-J2 SH-J3 SH-J4 SH-J5 SH-J6 SH-J7 SH-J8 SH-J9 SH-J10 SH-J11: library part CMP-0003761-2, "Shunt, 2.54mm, Gold, Black", Manufacturer="Wurth Elektronik", Supplier Part Number 1=732-2678-ND
TP1: library part CMP-0055147-2, "Test Point, Multipurpose, Red, TH", Color=Red, Manufacturer="Keystone Electronics", Supplier Part Number 1=36-5010-ND
TP2: library part CMP-0055148-2, "Test Point, Multipurpose, Black, TH", Color=Black, Manufacturer="Keystone Electronics", Supplier Part Number 1=36-5011-ND
TP3: library part CMP-0055150-2, "Test Point, Multipurpose, Orange, TH", Color=Orange, Manufacturer="Keystone Electronics", Supplier Part Number 1=36-5013-ND
TP4 TP5 TP6 TP7: library part CMP-0055139-2, "Test Point, Miniature, White, TH", Color=White, Manufacturer="Keystone Electronics", Supplier Part Number 1=36-5002-ND
TP8 TP9 TP10 TP11 TP12 TP13: library part CMP-0055149-2, "Test Point, Multipurpose, White, TH", Color=White, Manufacturer="Keystone Electronics", Supplier Part Number 1=36-5012-ND
U1 U2: library part CMP-0126978-1, Manufacturer="Texas Instruments", Operating Temperature Range=to
U3: library part CMP-0080370-1, "16 MHz Ultra-Low-Power Microcontroller With 1 KB FRAM, 0.5 KB SRAM, 12 IO, 8 ch 10-bit ADC, RLL0024A (VQFN-24)", Alternate Manufacturer="Texas Instruments", Alternate PartNumber=MSP430FR2100IRLLT
U4: library part CMP-0077328-2, "40-V Ultralow-Iq Low-Dropout Regulator, DBV0005A (SOT-23-5)", Alternate Manufacturer="Texas Instruments"
ZZ1: library part CMP-0077236-1
ZZ5: library part CMP-0003616-3

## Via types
v1: diameter 24, hole 12, Top Layer to Bottom Layer, tented both sides, 36 vias
v2: diameter 19.68, hole 7.87, Top Layer to Bottom Layer, tented both sides, 4 vias

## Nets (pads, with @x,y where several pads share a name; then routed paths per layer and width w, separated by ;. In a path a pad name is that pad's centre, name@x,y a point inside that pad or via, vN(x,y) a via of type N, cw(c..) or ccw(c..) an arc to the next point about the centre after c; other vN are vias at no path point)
GND: C1.1 C2.1 C3.2 C4.2 C5.2 C6.1 C7.2 C8.2 C9.1 C10.2 C11.2 C12.1 C13.2 C14.1 C16.1 C17.1 D3.1 D4.1 D5.1 J1.1 J2.1 J3.2 J4.1@2226,-70 J4.2@2226,-470 R2.1 R4.1 R9.1 R10.2 R11.2 RP1.1 RP2.1 TP2.1 U1.4 U1.9 U2.4 U2.9 U3.4 U3.25 U4.3 U4.4 | length 133.5
  Top Layer w7: C9.1@381.22,603.85 431.08,603.85 434.51,607.28 436.44,607.28 446.49,607.28 U3.4@446.93,607.72 485.31,607.72 U3.25@505,627.4
  other v2: 1604,428.84 1604,472.15 1589,1173.35 1589,1216.65
ID1: R1.1 R2.2 U3.17 | length 527.9
  Top Layer w7.5: U3.17@563.07,662.83 567.99,662.83 578.79,673.63 578.79,700.21 v1(578,701)
  Top Layer w10: R1.1@434.94,1069.75 433.82,1068.64 433.82,999.21 R2.2@432.71,998.1 432.76,998.05 v1(462,998) v1(462,998)
  Signal Layer 1 w7.5: v1(462,998) 485.62,974.38 542,974.38 578,938.38 v1(578,701)
ID2: R3.1 R4.2 U3.16 | length 514
  Top Layer w7.5: U3.16@563.07,647.09 589.62,647.09 595.54,653 v1(600,653)
  Top Layer w10: R3.1@514.94,1069.75 513.82,1068.64 513.82,999.21 R4.2@512.71,998.1 512.76,998.05 v1(544,998) v1(544,998)
  Signal Layer 1 w8: v1(544,998) 603,939 603,656 v1(600,653)
ID3: R8.1 R9.2 U3.15 | length 534.9
  Top Layer w7.5: U3.15@563.07,627.4 565.04,629.37 624.03,629.37 v1(626,631.34) ; R8.1@595.95,1069.75 594.84,1068.64 594.84,999.21 R9.2@593.73,998.1 593.78,998.05 v1(624,998) v1(624,998)
  Signal Layer 1 w8: v1(624,998) 626,996 v1(626,631.34)
IN1: J6.2 TP8.1 U1.6 | length 779.3
  Top Layer w8: 1523.83,459.13 1525.05,460.34 U1.6@1566.6,460.34
  Top Layer w12: TP8.1@1157,603 1157,541.41 1244.28,454.13 1518.83,454.13 1523.83,459.13
  Top Layer w16: J6.2@920,525 927.13,532.13 962.13,532.13 1033.27,603.27 TP8.1@1157,603
IN1_B: J5.2 TP4.1 U2.6 | length 682.3
  Top Layer w8: 1506.68,1204.69 U2.6@1551.6,1204.84
  Top Layer w14: J5.2@930,1200 1013.43,1200 TP4.1@1086.72,1273.28 1203.72,1273.28 1268.13,1208.87 1414.36,1208.87 1422.11,1201.13 1505.68,1201.13 1506.68,1202.13
IN2: J6.4 TP9.1 U1.5 | length 669.4
  Top Layer w8: 1530.02,480.02 U1.5@1566.6,480.02
  Top Layer w14: J6.4@920,425 1045.25,425 1062.25,442 TP9.1@1157,442 ; v1(1255,480) 1530,480
  Bottom Layer w14: TP9.1@1157,442 1176.04,442 1214.04,480 v1(1255,480)
IN2_B: J5.4 TP5.1 U2.5 | length 685.4
  Top Layer w8: 1514,1224 U2.5@1551.6,1224.53
  Top Layer w14: 1431.58,1224 1514,1224
  Top Layer w16: J5.4@930,1100 1029.9,1100 1073.19,1143.28 TP5.1@1086.72,1143.28 ; v1(1332,1239) 1416.58,1239 1431.58,1224
  Bottom Layer w16: TP5.1@1086.72,1143.28 1182.43,1239 v1(1332,1239)
MODE: J2.2 J6.6 TP10.1 U1.7 | length 1610.3
  Top Layer w8: 1500,430 1522.37,430 1533.02,440.65 U1.7@1566.6,440.65
  Top Layer w14: J2.2@108.76,167.48 214.62,273.34 868.34,273.34 J6.6@920,325 1109,325 TP10.1@1157,277 1160,277 1312,429 1500,430
MODE_B: J5.6 TP6.1 U2.7 | length 709.2
  Top Layer w8: 1506,1173 1518,1185 U2.7@1551.6,1185.16
  Top Layer w16: J5.6@930,1000 936.64,1006.64 1080.07,1006.64 TP6.1@1086.72,1013.28 1088,1012 1189,1012 1362,1185 1405.89,1185 1417.89,1173 1506,1173
MODE_MCU: J5.5 J6.5 U3.11 | length 1084.4
  Top Layer w7.5: v1(540,530) 540.25,530.25 540.25,569.14 U3.11@540.43,569.33
  Signal Layer 1 w12: v1(705,1000) 705,996.75 713,988.75 v1(713,476) 710.7,473.7 710.7,434.3 J6.5@820,325
  Signal Layer 2 w12: v1(540,530) 659,530 v1(713,476) ; v1(705,1000) J5.5@830,1000
NetC1_2: C1.2 R12.2 U4.1 | length 173.1
  Top Layer w12: C1.2@669.53,-445 669.53,-394.13 686.26,-377.4 U4.1@694.13,-377.4 733.98,-377.4 766.46,-344.92 R12.2@766.46,-340
NetD1_1: D1.1 R10.1 | length 279.9
  Top Layer w12: R10.1@428.62,485 665,485 673.5,493.5 D1.1@673.5,525
NetD2_1: D2.1 R11.1 | length 244.9
  Top Layer w12: R11.1@428.62,430 D2.1@673.5,430
NetD3_2: D3.2 R5.2 | length 70
  Top Layer w12: R5.2@1133.5,-440 D3.2@1133.5,-370
NetD4_2: D4.2 R6.2 | length 72.6
  Top Layer w20: D4.2@718.5,-30 718.5,-86.06 727.44,-95 R6.2@731.38,-95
